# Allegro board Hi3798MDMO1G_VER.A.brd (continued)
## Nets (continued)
$16N1158: J25.11 R79.1
$16N1159: J25.7 J25.8 R270.2
$16N1160: R271.2 T2.15
$16N1161: R269.2 T2.10
$16N1163: J25.6 T2.9
$16N1164: J25.3 T2.11
$16N1165: C23.1 R269.1 R270.1 R271.1 R272.1
$16N1166: J25.1 T2.16
$16N1167: J25.2 T2.14
$16N1168: J25.4 J25.5 R272.2
$16N1169: C153.1 C307.1 T2.2
$16N1187: R61.2 T2.1
$16N1188: R62.2 T2.3
$16N1189: R63.2 T2.6
$16N1190: R64.2 T2.8
$18N880: D19.1 R268.1

Pads without a net: ID1 1; ID2 1; ID3 1; ID4 1; ID5 1; ID6 1; J2 1 6 8 11; J26 14; J34 6; M20 1; M21 1; M22 1; M23 1; T2 4 5 12 13; U1 14 15 56 99 100 101; U2 3; U3 J1 J9 L1 L9; U6 J1 J9 L1 L9; U7 4 9 10; U11 5; U13 5; U19 3 4 5 6 10 11 14 15 20 21 22 26 27 28 33 35 40 45 46 47; U22 1 2 A4 A6 A9 A11 AA1 AA2 AA7 AA8 AA9 AA10 AA11 AA12 AA13 AA14 AE1 AE14 AG2 AG13 AH4 AH6 AH9 AH11 B2 B13 D1 D14 H1 H2 H6 H7 H8 H9 H10 H11 H12 H13 H14 J1 J7 J8 J9 J10 J11 J12 J13 J14 K1 K3 K5 K7 K8 K9 K10 K11 K12 K13 K14 L1 L2 L3 L4 L12 L13 L14 M1 M2 M3 M5 M8 M9 M10 M12 M13 M14 N1 N2 N3 N10 N12 N13 N14 P1 P2 P3 P10 P12 P13 P14 R1 R2 R3 R5 R12 R13 R14 T1 T2 T3 T5 T12 T13 T14 U1 U2 U3 U6 U7 U10 U12 U13 U14 V1 V2 V3 V12 V13 V14 W1 W2 W3 W7 W8 W9 W10 W11 W12 W13 W14 Y1 Y3 Y6 Y7 Y8 Y9 Y10 Y11 Y12 Y13 Y14

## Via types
v1: diameter 0.508, hole 0.254, TOP to BOTTOM, 1049 vias
v2: diameter 0.457, hole 0.203, TOP to BOTTOM, 246 vias

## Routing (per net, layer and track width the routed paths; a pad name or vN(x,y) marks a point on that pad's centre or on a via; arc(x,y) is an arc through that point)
1V1_CORE: length 70.2
  TOP w0.203: U1.168 v1(46.25,43.78) ; U1.30 v1(58.75,23.65) ; v1(48.35,46.74) 48.75,47.13 U1.158 ; v1(48.48,23.65) 48.35,23.52 U1.4 ; U1.134 58.35,47.03 58.64,46.74 v1(59.02,46.74) ; U1.39 v1(62.35,23.65) ; U1.49 66.35,23.24 65.97,23.62 v1(65.37,23.62) ; U1.10 v1(50.75,23.65) ; U1.186 45.99,36.58 v1(46.25,36.83) ; U1.105 v1(69.36,44.58) ; v1(69.31,33.53) 69.56,33.78 U1.78 ; U1.180 v1(46.25,38.98) ; U1.214 v1(46.25,25.38) ; U1.193 v1(46.25,33.78) ; U1.202 v1(46.25,30.18) ; U1.118 64.75,46.93 v1(64.88,46.8) ; U1.86 v1(69.31,36.98)
  TOP w0.381: v1(57.88,9.65) R101.2 C82.2
  BOTTOM w0.381: v1(48.48,42.67) 47.34,43.81 46.21,43.81 ; C1.1 v1(65.37,23.62) ; C62.1 v1(59.02,46.74) 59.04,46.72 LB31.1 ; 46.24,36.83 v1(48.86,36.83) ; 46.24,36.83 v1(46.25,36.83) ; 46.24,36.83 C127.1 ; v1(66.36,31.14) 66.11,30.88 LB21.1 ; v1(69.36,44.58) 69.56,44.58 69.57,44.58 C189.1 ; C128.1 46.13,38.86 v1(46.25,38.98) v1(48.86,38.98) ; C73.1 62.45,23.55 v1(62.35,23.65) ; C107.1 46.24,33.78 v1(46.25,33.78) v1(48.86,33.78) ; v1(48.35,46.74) C130.1 ; C120.1 46.23,25.4 v1(46.25,25.38) v1(48.86,25.38) ; v1(69.31,36.98) 69.33,36.96 C121.1 ; v1(48.48,23.65) 48.35,23.52 C70.1 ; v1(50.75,23.65) 50.77,23.63 C66.1 ; 69.18,19.68 64.8,15.3 59.52,15.3 57.88,13.67 v1(57.88,9.65) ; 46.21,43.81 v1(46.25,43.78) ; 46.21,43.81 C129.1 ; v1(58.75,23.65) 58.77,23.63 C64.1 ; C193.1 46.2,30.23 v1(46.25,30.18) v1(48.86,30.18)
  vias: v1(63.72,45.97) v1(63.72,45.09) v1(68.29,24.89) v1(68.93,24) v1(69.18,23.11) v1(69.31,21.08) v1(70.71,23.62) v1(70.71,21.97)
1V1_CPU: length 13.3
  TOP w0.203: U1.98 71.62,41.78
  TOP w0.254: R53.2 62.48,56.5 62.99,55.99 C76.2 63.4,55.46 63.4,54.32 66.77,50.95 69.72,50.95 70.33,51.56 70.83,51.56
  vias: v1(72.23,41.66) v1(72.23,40.77) v1(72.23,39.88) v1(72.99,50.8) v1(72.99,49.91) v1(73.25,41.66) v1(73.25,40.77) v1(73.25,39.88) v1(73.88,50.8) v1(73.88,49.91) v1(74.64,39.75) v1(74.77,50.8) v1(74.77,49.91)
1V5_DDR3: length 100
  TOP w0.203: U1.35 v1(60.75,23.65) ; v2(35.91,26.04) 35.09,26.86 35.09,27.2 35.44,27.55 35.44,27.62 35.47,27.65 U6.H2 ; U1.165 v1(46.32,44.98) ; U1.190 v1(46.25,34.98) ; U1.25 v1(56.75,23.65) ; U1.44 v1(64.35,23.65) ; U1.183 v1(46.25,37.78) ; v1(66.64,23.62) 67.72,23.62 67.95,23.39 U1.53 ; U1.205 v1(46.25,28.98) ; U1.199 v1(46.25,31.38) ; U1.174 v1(46.25,41.38) ; U1.7 v1(49.55,23.65) ; U1.208 v1(46.25,27.78) ; U1.171 v1(46.25,42.58) ; U1.13 v1(51.95,23.65) ; U1.196 v1(46.25,32.58) ; U1.1 v1(47.1,23.65) ; U1.16 v1(53.15,23.65)
  TOP w0.254: U6.K2 v2(34.27,27.44) ; U3.R1 v2(29.47,44.65) ; U3.N1 v2(31.07,44.65) ; U3.K2 v2(33.47,44.65)
  TOP w0.305: U6.C9 v2(39.47,21.69) ; U6.K8 v2(33.46,22.64) ; U6.N9 v2(31.47,21.69) ; v2(37.07,29.19) 37.07,28.64 U6.F1 ; U6.A1 41.07,28.64 v2(41.07,29.19) ; U3.C1 v2(39.47,45.6) ; U6.H9 35.47,21.73 35.46,21.72 v2(35.42,21.72) ; U3.N9 v2(31.47,38.03) ; U6.R9 v2(29.87,21.69) ; U6.B2 v2(40.66,27.46) ; U3.G7 v2(36.67,40.65) ; U6.N1 v2(31.47,29.19) ; U6.R1 v2(29.87,29.19) ; U6.E9 v2(37.87,21.69) ; v2(38.26,44.65) 38.66,44.25 U3.D2 ; U3.A8 v2(40.67,39.05) ; U3.B2 40.27,44.27 v2(39.88,44.66) ; U3.H9 v2(35.47,38.11) ; U3.D9 v2(39.07,38.25) ; U3.R9 v2(29.87,38.1) ; U6.C1 v2(39.47,29.19) ; U3.E9 v2(38.27,38.25) ; U3.K8 v2(33.47,39.05) ; U3.A1 v2(41.07,45.6) ; U6.D2 v2(39.06,27.46) ; U3.H2 v2(35.06,43.85) ; U6.A8 v2(41.65,23.04) ; U3.F1 v2(37.07,45.63) ; U6.D9 v2(38.67,21.69) ; U6.G7 v2(36.68,24.25) ; U3.C9 v2(39.87,38.25)
  TOP w0.381: 22.07,39.12 22.07,38.1 21.6,37.64 14.16,37.64 C84.2 R10.2 ; R92.1 C103.1 32.12,18.26 v2(31.72,18.67) ; v2(31.88,35.18) 32.16,34.9 C100.1 R60.1
  BOTTOM w0.254: v2(33.46,22.64) 33.7,22.4 C226.1 ; C240.1 37.71,21.85 v2(37.87,21.69) ; C225.1 35.88,22.18 v2(35.42,21.72)
  BOTTOM w0.305: C231.1 39.82,22.04 v2(39.47,21.69) ; v2(41.65,23.04) 41.52,22.92 C238.1 ; C229.1 34.28,27.43 v2(34.27,27.44) ; v2(29.87,38.1) 29.87,37.51 C216.1 ; v2(31.47,38.03) 31.47,37.51 C213.1 ; v2(33.47,39.05) 33.49,39.08 C212.1 ; C239.1 38.9,21.93 v2(38.67,21.69)
  BOTTOM w0.381: v2(40.67,39.05) 40.71,39.01 C218.1 ; C219.1 39.84,38.23 v2(39.87,38.25) ; v2(33.47,44.65) 33.09,44.27 C201.1 ; v2(41.07,29.19) 41.37,28.89 C235.1 ; C202.1 41.52,46.01 41.12,45.6 v2(41.07,45.6) ; C206.1 35.54,38.04 v2(35.47,38.11) ; v2(39.88,44.66) 39.95,44.73 C205.1 ; v2(39.47,45.6) 39.74,45.88 C203.1 ; v2(36.68,24.25) 36.61,24.19 C258.1 ; v2(38.26,44.65) 38.45,44.46 C204.1 ; C211.1 v2(36.67,40.65) ; C215.1 29.53,44.71 v2(29.47,44.65) ; v2(29.87,29.19) 29.87,29.82 C233.1 ; C228.1 29.87,20.92 v2(29.87,21.69) ; v1(53.15,23.65) 53.18,23.62 C97.1 ; R54.1 v2(33.97,47.58) ; C52.1 46.21,42.55 v1(46.25,42.58) ; v2(38.27,38.25) 38.06,38.05 C221.1 ; v2(39.06,27.46) 38.9,27.62 C237.1 ; v1(46.25,34.98) 46.07,34.8 C48.1 ; v1(51.95,23.65) 51.91,23.61 C109.1 ; v1(46.25,27.78) 46.21,27.81 C125.1 ; C20.1 66.82,23.44 v1(66.64,23.62) ; C101.1 46.24,31.37 v1(46.25,31.38) ; v2(37.07,29.19) 36.71,28.83 C232.1 ; C236.1 40.52,27.59 v2(40.66,27.46) ; v1(46.25,28.98) 46.22,28.96 C94.1 ; v1(46.25,37.78) 46.18,37.85 C49.1 ; v2(37.07,45.63) 37.07,45.39 C209.1 ; v1(47.1,23.65) 47.08,23.63 C96.1 ; v1(56.75,23.65) 56.74,23.63 C137.1 ; C98.1 46.18,32.51 v1(46.25,32.58) ; C234.1 39.66,29 v2(39.47,29.19) ; C102.1 60.8,23.6 v1(60.75,23.65) ; R78.1 v2(37.13,33.05) ; v2(31.47,29.19) 31.47,29.78 C230.1 ; v1(64.35,23.65) 64.35,23.64 64.1,23.64 63.85,23.39 C104.1 ; v1(46.25,41.38) 46.22,41.4 C99.1 ; C210.1 35.57,43.34 v2(35.06,43.85) ; v2(31.47,21.69) 31.47,21.11 C227.1 ; C223.1 v2(37.13,32.16) ; v2(39.07,38.25) 38.95,38.14 C220.1 ; v2(31.07,44.65) 31.23,44.81 C214.1 ; C117.1 49.62,23.58 v1(49.55,23.65) ; C208.1 v2(34.86,47.58) ; v1(46.32,44.98) 46.3,44.96 C92.1
  vias: v1(23.41,41.25) v1(23.41,39.88) v1(24.02,39.24) v1(24.05,42.95) v1(24.05,41.96) v1(24.07,40.51) v2(35.91,25.32) v2(36.54,41.59) v2(37.43,41.59) v2(44.67,22.99) v2(44.67,22.1) v2(45.56,22.99) v2(45.56,22.1) v2(46.45,22.99) v2(46.45,22.1)
3V3: length 23.3
  TOP w0.203: v1(71.85,28.7) 71.73,28.58 U1.65
  TOP w0.381: v1(64.76,10.54) 64.79,10.52 64.79,10.49 64.97,10.31 R31.1 ; R136.1 v1(78.68,4.65) ; R6.1 v1(14.39,39.29) ; R140.2 v1(67.79,7.24) ; R2.1 v1(57.88,7.11) ; J18.4 76.88,4.02 R135.1 v1(76.04,5.33) ; R178.2 v1(69.06,7.11) ; R34.1 v1(66.8,5.97)
  BOTTOM w0.381: v1(65.98,68.86) 65.3,68.86 R105.2 ; R88.2 73.27,26.26 72.99,26.54 v1(72.87,26.54) ; Q13.2 67.4,9.78 v1(66.9,9.27) ; v1(14.39,39.29) 14.13,39.54 14.13,44.88 C114.1
  vias: v1(12.12,46.38) v1(12.12,45.61) v1(12.12,44.85) v1(12.89,46.38) v1(12.89,45.61) v1(12.89,44.85) v1(59.96,14.35) v1(60.6,12.7) v1(60.67,13.79) v1(61.36,13.13) v1(61.69,13.98) v1(62.83,14.1) v1(66.64,69.93) v1(67.02,59.19) v1(67.15,69.16) v1(67.66,69.93) v1(67.91,59.19) v1(68.17,69.16) v1(68.67,69.93) v1(68.8,59.19) v1(69.18,69.16) v1(69.69,69.93) v1(69.69,59.19) v1(70.58,59.19)
3V3_MOS: length 54.3
  TOP w0.203: v1(69.31,31.93) 69.56,32.18 U1.74 ; U1.120 63.95,47.01 64,46.96 v1(64,46.77) ; v1(69.37,43.69) 69.37,43.81 69.73,44.18 U1.104 ; U1.83 v1(69.31,35.78)
  TOP w0.381: v1(62.96,72.77) 62.96,72.58 62.77,72.39 D9.2 61.51,72.08 v1(61.51,70.1) ; v1(47.68,66.04) D19.2 ; v1(17.81,63.93) R26.1 18.2,64.7 18.58,65.09 18.58,67.99 17.94,68.63 17.94,75.25 19.5,76.8 J25.10 ; v1(65.88,75.82) R25.1 ; J25.12 32.61,76.8 33.33,76.08 33.33,64.53 33.59,64.27 R30.1 34.04,63.79 31.74,61.49 v1(31.69,61.49)
  BOTTOM w0.381: v1(18.25,60.37) 18.25,63.49 v1(17.81,63.93) ; v1(64,46.77) C197.1 63.98,47.52 R39.2 ; C199.1 69.36,31.88 v1(69.31,31.93) ; v1(65.88,75.82) 65.88,75.69 v1(62.96,72.77)
  vias: v1(14.06,53.77) v1(14.06,53.01) v1(18.25,59.23) v1(20.23,26.72) v1(52.29,43.31) v1(52.29,42.42) v1(55.29,43.1) v1(55.29,42.21) v1(58.26,28.19) v1(58.26,27.3) v1(60.04,58.27) v1(60.04,57.38) v1(60.42,43.43) v1(60.42,42.55) v1(65.37,28.19) v1(65.37,27.3) v1(65.75,36.45) v1(65.75,35.56) v1(66.01,12.57) v1(66.9,12.57) v2(20.23,25.7) v2(21.12,26.72) v2(21.12,25.7)
3V3_MOS_FLASH: length 42.1
  TOP w0.203: U22.Y4 U22.AA3
  TOP w0.254: U19.1 90.11,44.68 89.76,44.32 v1(87.72,44.32) ; v1(80.49,45.09) 79.09,45.09 78.61,45.56 U19.24 ; U19.37 84.61,28.01 v1(84.61,28.01) ; 85.11,35.9 v2(85.07,35.94) ; 85.11,35.9 85.13,35.87 U22.N5 ; 85.11,35.9 U22.M6 ; U22.K6 85.11,34.5 v2(84.75,34.86) 82.94,34.86 82.58,35.22 82.58,37 82.95,37.37 U22.T10 83.62,37.37 v2(83.64,37.36) 83.64,37.84 U22.U9 83.61,38.02 v2(83.28,38.35) ; v1(83.11,25.36) U19.34 ; 84.61,45.33 U19.12 ; v2(85.74,40.43) 85.61,40.3 U22.AA5 ; U22.AA3 86.61,39.89 v2(87.15,40.43) ; R68.2 84.96,24.18 83.97,24.18 83.64,24.51 R80.1 ; U22.Y4 U22.W4 v2(86.11,38.34)
  TOP w0.381: v2(87.15,40.43) 87.15,41.22 86.75,41.63 86.04,41.63 85.74,41.32 v2(85.74,40.43) ; v1(83.03,24.38) 83.41,24.77 R80.1 ; v2(84.48,43.4) 84.61,43.53 84.61,45.33
  BOTTOM w0.381: C275.1 84.68,34.8 v2(84.75,34.86) ; v2(83.64,37.36) 83.63,37.36 C105.1 ; C93.1 85.31,36.19 v2(85.07,35.94) ; v2(84.48,43.4) 84.07,43.81 82.39,43.81 81.76,44.45 81.76,44.7 81.37,45.09 v1(80.49,45.09) ; R212.1 83.32,38.39 v2(83.28,38.35) ; v2(85.74,40.43) 85.68,40.37 C323.1 86.11,39.29 v2(86.11,38.34)
  vias: v1(75.15,58.93) v1(75.15,58.04) v1(76.04,58.93) v1(76.04,58.04)
3V3_SD:
  vias: v1(10.27,56.08) v1(10.27,55.29)
3V3_WIFI:
  vias: v1(14.26,27.48) v1(15.15,27.48)
5V0: length 11.8
  TOP w0.254: v1(74.01,13.34) 73.88,13.21 R144.1
  BOTTOM w0.381: v1(72.48,62.99) 71.01,62.99 70.2,62.18 D4.2 69.88,61.43 63.79,61.43 R4.1
  vias: v1(73.25,13.84) v1(73.25,12.83) v1(74.71,72.06) v1(74.71,71.17) v1(74.71,70.28) v1(75.6,72.06) v1(75.6,71.17) v1(75.6,70.28) v1(76.49,72.06) v1(76.49,71.17) v1(76.49,70.28)
5V0_MOS: length 21.6
  TOP w0.381: D20.2 v1(52.87,77.1) ; R11.2 v1(75.36,14.73) ; R15.2 v1(80.49,69.09)
  BOTTOM w0.381: v1(80.49,69.09) 80.1,68.71 73.88,68.71 72.05,70.54 64.79,70.54 63.47,69.22 R179.1
  vias: v1(78.45,74.8) v1(79.34,74.8) v1(80.23,74.8) v1(80.36,13.21) v1(80.36,12.32) v1(80.36,11.43)
5V0_MOS_HDMI: length 14
  TOP w0.254: 49.41,78.17 49.17,78.41 J26.18
  TOP w0.381: U4.5 v1(50.96,73.42) 51.68,73.42 52.1,73.84 D20.1 52.1,75.1 51.48,75.73 R187.2 v1(50.73,76.49) 49.41,77.81 49.41,78.17 ; R186.2 v1(48.95,76.49)
  BOTTOM w0.381: v1(50.96,73.42) 50.88,73.34 C150.1 ; v1(48.95,76.49) v1(50.73,76.49)
AVDD11_PLL012: length 1.5
  TOP w0.203: v1(69.39,30.35) 69.39,30.07 69.68,29.78 U1.68
AVDD33_PLL01: length 1.3
  TOP w0.203: U1.66 69.69,28.98 69.39,28.68 v1(69.39,28.57)
AVDD33_USB2: length 1.4
  TOP w0.203: v1(69.31,38.16) 69.31,38.03 69.56,37.78 U1.88
GND: length 633.7
  TOP w0.089: 88.12,39.62 87.36,39.62 U22.Y2
  TOP w0.203: U1.62 72.03,27.38 v1(72.23,27.18) ; v1(54.2,21.34) 54.35,21.49 U1.19 ; U1.94 v1(69.31,40.18) ; U1.97 v1(69.31,41.38) ; U1.177 v1(43.91,40.18) ; 35.06,40.55 35.06,39.85 U3.J8 ; U22.AA6 U22.Y5 U22.AA4 ; v1(69.39,29.38) U1.67 71.51,29.38 v1(71.72,29.59) ; v2(34.38,24.29) 34.28,24.18 34.28,23.63 34.67,23.24 U6.J8 ; U1.115 v1(65.95,48.99) ; U1.110 67.95,48.73 67.72,48.96 v1(67.53,48.96) ; U1.211 v2(43.82,26.58)
  TOP w0.229: U22.K4 85.62,34.86 v2(85.57,34.86)
  TOP w0.254: v1(69.06,51.44) 67.15,51.44 v1(65.25,53.34) ; v2(84.84,40.46) 85.11,40.19 U22.AA6 ; v1(83.65,28.01) 83.9,28.01 84.11,27.8 U19.36 ; J26.11 v1(45.67,78.31) ; v1(71.34,50.93) 71.85,50.42 C72.2 ; U3.E2 37.79,44.33 37.79,44.97 U3.E1 ; R149.2 v1(27.8,50.56) ; v2(86.45,41.04) 86.44,41.04 86.44,40.48 86.11,40.15 U22.AA4 ; J26.2 v1(41.17,78.31) ; J26.8 v1(44.17,78.31) ; v1(79.11,47.53) U19.23 ; U3.M1 v2(32.67,44.65) ; U19.48 v1(90.11,28.07) ; v1(78.61,28.19) U19.25 ; J26.17 v1(48.67,78.31) ; v1(89.48,45.09) 89.61,45.21 U19.2 ; J26.5 v1(42.67,78.31) ; 83.96,45.13 84.11,45.28 U19.13 ; U3.P1 v2(30.27,44.65) ; U6.J2 v2(34.27,28.24) ; U3.J2 v2(35.07,44.65) ; U3.T1 v2(28.67,44.65)
  TOP w0.305: U3.P9 v2(30.27,39.05) ; U3.F9 v2(37.07,38.11) ; v2(40.73,26.5) 40.27,26.97 U6.B3 ; U3.B9 v2(39.87,39.05) ; U3.M9 v2(32.27,38.1) ; v2(40.36,21.72) 40.27,21.81 U6.B9 ; U3.G1 v2(36.27,45.63) ; v2(36.24,21.69) 36.29,21.69 36.27,21.72 U6.G9 ; U3.A9 v2(40.67,38.25) ; U3.D1 v2(38.26,45.46) 37.87,45.07 U3.E1 ; U6.B1 v2(40.27,29.19) ; U6.A9 41.07,22.14 v2(41.5,21.72) ; U3.D8 v2(39.07,39.05) ; v1(42.53,76.08) v1(42.53,74.62) v1(42.53,73.01) ; U6.G1 v2(36.27,29.61) ; U3.G9 v2(36.27,38.11) ; v1(40.93,73.06) U23.3 U23.8 v1(40.93,76.09) ; U6.E8 v2(38.27,23.44) U6.D8 ; U6.P9 v2(30.67,21.69) ; v2(37.07,21.69) 37.09,21.69 37.07,21.72 U6.F9 ; v1(44.11,76.04) U24.8 U24.3 v1(44.11,73.06) ; U6.T1 v2(28.68,29.03) ; v2(35.47,41.01) 35.06,40.61 35.06,40.55 ; U6.D1 v2(38.67,29.19) ; U6.E1 37.87,28.62 v2(38.26,28.23) U6.E2 ; v2(25.62,26.16) 26.05,26.59 C314.2 ; U3.E8 v2(38.27,39.05) ; U6.M1 v2(32.27,29.19) ; U6.P1 v2(30.67,29.19) ; U3.B3 40.27,43.47 v2(39.88,43.86) ; U6.T9 v2(29.07,21.69) ; U3.G8 v2(36.67,39.85) ; U3.B1 v2(40.27,45.6) ; U6.M9 v2(32.27,21.69) ; U6.G8 v2(36.68,23.45) ; U3.T9 v2(29.07,38.1)
  TOP w0.356: U5.10 v1(58.71,68.89) ; 56.45,72.1 v1(56.45,72.06) ; 56.45,72.1 R146.2 ; 56.45,72.1 55.83,71.49 v1(55.15,71.49) U5.1 ; R145.2 v1(57.54,72.06) 58.11,71.49 v1(58.58,71.49) U5.14 ; v1(55.21,68.96) 55.21,69.28 54.96,69.54 U5.4
  TOP w0.381: C5.2 v1(65.78,10.64) ; R24.1 v1(74.64,36.58) R87.1 ; v1(57.88,58.42) 57.59,58.71 R50.2 ; v1(61.72,10.64) 61.05,10.64 R13.1 ; R9.2 C79.2 v1(64.08,71.75) ; C158.2 63.21,67.44 63.85,68.07 v1(63.85,68.33) ; 83.96,45.13 83.11,44.28 83.11,42.87 v2(83.02,42.77) ; v2(36.77,34.9) R55.2 C86.2 ; C118.2 v1(80.49,5.71) ; R51.2 64,10.64 v1(63.72,10.92) ; v2(36.04,18.26) R93.2 C87.2 ; C22.2 v1(47.47,51.94) ; U4.2 v1(46.23,73.42) ; C141.2 v1(78.83,60.5) ; Q4.2 v1(68.93,9.02) ; C33.1 v1(51.32,66.93) ; R52.2 v1(10.45,38.37) ; C71.2 v1(67.91,50.42) ; C365.2 v1(77.06,22.12) ; v1(59.28,6.73) 59.27,6.74 Q1.2 ; J21.14 v1(11.34,48.07) ; C364.2 73.5,21.34 v1(73.25,21.59) ; v1(58.39,62.6) C316.2 ; D1.2 v1(80.61,64.01) ; C139.2 v1(78.71,63.22) ; X2.2 v1(78.71,18.07) ; R48.1 v1(82.52,69.95) ; R99.1 63.21,58.04 ; v1(64.23,7.62) 63.8,8.05 Q2.2 ; v1(66.77,18.8) 66.9,18.92 C37.2 67.85,19.37 67.63,19.58 R45.2 67.63,20.55 68.04,20.95 v1(68.04,21.21) ; R57.2 v1(62.3,71.25) ; C177.2 v1(72.99,6.38) ; C363.2 v1(50.64,68.07) ; v1(55.26,58.37) 54.93,58.7 R183.2 ; C317.2 v1(53.76,62.6) ; U11.2 v1(65.12,56.64) ; D6.2 v1(81.37,60.5)
  TOP w0.508: v1(10.12,57.32) 9.8,57.64 J21.6 7.87,57.64 ; J12.5 85.79,57.24 ; J12.5 87.75,55.28 ; J12.5 85.79,53.33 ; J12.5 83.83,55.28 ; J12.6 87.75,68.42 ; J12.6 83.83,68.42 ; J12.6 85.79,66.47 ; J12.6 85.79,70.38 ; J12.4 83.08,66.42 ; J12.4 81.7,65.35 ; J12.4 84.46,65.35 ; J12.4 83.08,64.29 ; LED1.2 v1(62.09,5.21)
  TOP w0.635: J34.5 63.36,77.65 ; J34.5 62.11,79.25 ; J34.5 62.11,76.05 ; S1.4 65.75,83.35 ; S1.4 64.3,81.9 ; S1.4 65.75,80.46 ; S1.1 71.5,85.6 ; S1.1 72.69,84.4 ; S1.1 71.5,83.21 ; S1.1 70.31,84.4 ; J1.2 75.57,82.31 ; J1.2 76.84,80.2 ; J1.2 75.57,78.09 ; J1.2 74.3,80.2 ; 78.49,85.38 J10.2 ; J10.2 80.37,86.66 ; J10.2 82.25,85.38 ; J26.21 39.12,80.8 ; J26.21 37.92,78.72 ; J26.21 36.73,80.8 ; J26.21 37.92,82.88 ; S1.3 74.2,81.9 ; S1.3 71.3,81.9 ; S1.3 72.75,83.35 ; S1.3 72.75,80.46 ; J26.20 52.42,82.88 ; J26.20 53.62,80.8 ; J26.20 52.42,78.72 ; J26.20 51.23,80.8 ; J13.4 82.3,18.79 ; J13.4 82.3,16.75 ; J13.4 83.63,17.77 ; J13.4 80.97,17.77 ; 80.63,1.24 J18.1 ; J18.1 81.44,2.24 ; J18.1 80.63,3.25 ; 85.01,18.94 J13.6 ; J13.6 86.91,20.84 ; J13.6 83.1,20.84 ; 51.23,86.76 J26.22 ; J26.22 53.62,86.76 ; J26.22 52.42,84.93 ; 37.92,84.93 J26.23 ; J26.23 36.73,86.76 ; J26.23 39.12,86.76 ; 82.48,83.7 J1.3 80.37,82.48 ; 85.01,5.74 J13.5 ; J13.5 86.97,7.7 ; J13.5 85.01,9.66 ; J13.5 83.05,7.7 ; 77.67,81.3 J10.3 ; J10.3 77.67,85.06 ; J10.3 76.39,83.18
  GND02 w0.635: J18.1 80.63,3.17 ; J18.1 80.63,1.32 ; J18.1 81.37,2.24 ; J12.4 84.39,65.35 ; J12.4 81.77,65.35 ; J12.4 83.08,64.36 ; J12.4 83.08,66.34 ; 69.58,1.13 D3.2 ; D3.2 70.57,2.12 ; D3.2 69.58,3.11 ; D3.2 68.59,2.12 ; 20.03,34.4 J2.2 20.03,36.64 ; J12.6 85.79,70.3 ; J12.6 85.79,66.54 ; J12.6 87.67,68.42 ; J12.6 83.91,68.42 ; 10.43,8.52 J2.7 ; J2.7 11.42,7.53 ; J2.7 11.42,9.51 ; 85.01,5.82 J13.5 ; J13.5 86.89,7.7 ; J13.5 85.01,9.58 ; J13.5 83.13,7.7 ; J2.10 19.7,9.51 ; J2.10 18.71,8.52 ; J2.10 19.7,7.53 ; 72.75,80.53 S1.3 ; S1.3 71.38,81.9 ; S1.3 72.75,83.28 ; S1.3 74.12,81.9 ; 85.01,18.96 J13.6 ; J13.6 85.01,22.72 ; J13.6 86.89,20.84 ; J13.6 83.13,20.84 ; 62.11,76.13 J34.5 ; J34.5 63.28,77.65 ; J34.5 62.11,79.18 ; J2.12 22.7,9.51 ; J2.12 22.7,7.53 ; J2.12 23.69,8.52 ; 87.94,51.18 J3.1 ; J3.1 90.3,51.18 ; J3.1 89.12,52.36 ; J3.1 89.12,50 ; 62.09,1 LED1.2 ; LED1.2 60.97,2.12 ; LED1.2 62.09,3.24 ; LED1.2 63.2,2.12 ; J26.20 52.42,82.81 ; J26.20 52.42,78.79 ; J26.20 51.3,80.8 ; J26.20 53.54,80.8 ; S1.4 67.12,81.9 ; S1.4 65.75,80.53 ; S1.4 65.75,83.28 ; S1.4 64.38,81.9 ; J10.2 80.37,86.63 ; J10.2 78.52,85.38 ; J10.2 82.23,85.38 ; 75.57,78.12 J1.2 ; J1.2 75.57,82.28 ; J1.2 76.82,80.2 ; J1.2 74.33,80.2 ; S1.1 71.5,85.52 ; S1.1 70.38,84.4 ; S1.1 71.5,83.29 ; S1.1 72.62,84.4 ; J12.5 85.79,57.16 ; J12.5 83.91,55.28 ; J12.5 87.67,55.28 ; J12.5 85.79,53.4 ; 52.42,85.01 J26.22 ; J26.22 51.3,86.76 ; J26.22 53.54,86.76 ; 36.8,80.8 J26.21 ; J26.21 39.04,80.8 ; J26.21 37.92,82.81 ; J26.21 37.92,78.79 ; 80.37,82.5 J1.3 82.46,83.7 ; 36.8,86.76 J26.23 ; J26.23 39.04,86.76 ; J26.23 37.92,85.01 ; 77.67,81.32 J10.3 ; J10.3 76.42,83.18 ; J10.3 77.67,85.03 ; J2.9 15.41,8.52 ; J2.9 14.42,7.53 ; J2.9 14.42,9.51 ; 80.99,17.77 J13.4 ; J13.4 82.3,18.76 ; J13.4 82.3,16.78 ; J13.4 83.61,17.77
  POWER03 w0.635: 37.92,85.01 J26.23 ; J26.23 39.04,86.76 ; J26.23 36.8,86.76 ; J18.1 80.63,3.17 ; J18.1 81.37,2.24 ; J18.1 80.63,1.32 ; J13.5 85.01,9.58 ; J13.5 86.89,7.7 ; J13.5 83.13,7.7 ; J13.5 85.01,5.82 ; 51.3,86.76 J26.22 ; J26.22 53.54,86.76 ; J26.22 52.42,85.01 ; S1.1 72.62,84.4 ; S1.1 70.38,84.4 ; S1.1 71.5,83.29 ; S1.1 71.5,85.52 ; S1.4 67.12,81.9 ; S1.4 65.75,83.28 ; S1.4 65.75,80.53 ; S1.4 64.38,81.9 ; S1.3 74.12,81.9 ; S1.3 72.75,83.28 ; S1.3 71.38,81.9 ; S1.3 72.75,80.53 ; J10.3 77.67,85.03 ; J10.3 77.67,81.32 ; J10.3 76.42,83.18 ; D3.2 69.58,3.11 ; D3.2 70.57,2.12 ; D3.2 68.59,2.12 ; D3.2 69.58,1.13 ; J3.1 90.3,51.18 ; J3.1 89.12,52.36 ; J3.1 89.12,50 ; J34.5 63.28,77.65 ; J34.5 62.11,79.18 ; J34.5 62.11,76.13 ; J26.20 53.54,80.8 ; J26.20 52.42,82.81 ; J26.20 51.3,80.8 ; J26.20 52.42,78.79 ; 83.91,68.42 J12.6 ; J12.6 87.67,68.42 ; J12.6 85.79,66.54 ; J12.6 85.79,70.3 ; J2.7 11.42,9.51 ; J2.7 11.42,7.53 ; J2.7 10.43,8.52 ; J10.2 82.23,85.38 ; J10.2 80.37,86.63 ; J10.2 78.52,85.38 ; 75.57,78.12 J1.2 ; J1.2 76.82,80.2 ; J1.2 74.33,80.2 ; J1.2 75.57,82.28 ; J2.9 15.41,8.52 ; J2.9 14.42,9.51 ; J2.9 14.42,7.53 ; 82.46,83.7 J1.3 80.37,82.5 ; 36.8,80.8 J26.21 ; J26.21 37.92,78.79 ; J26.21 37.92,82.81 ; J26.21 39.04,80.8 ; LED1.2 63.2,2.12 ; LED1.2 62.09,1 ; LED1.2 62.09,3.24 ; LED1.2 60.97,2.12
  BOTTOM w0.254: v2(37.07,21.69) 36.75,22.02 C225.2 ; C240.2 37.97,23.15 v2(38.27,23.44) ; 55.29,48.45 55.28,48.45
  BOTTOM w0.305: v2(40.36,21.72) 40.36,21.99 C238.2 ; C313.2 27.98,44.41 28.2,44.64 28.66,44.64 v2(28.67,44.65) ; v2(33.12,41.2) 33.12,41.01 33.49,40.64 C212.2 ; v2(30.29,31.22) 29.83,30.77 C233.2 ; v2(34.38,25.47) 34.38,25.94 C229.2 ; v2(38.27,23.44) 38.57,23.15 C239.2 C231.2 ; v2(33.12,41.91) 32.98,42.04 R46.1 ; R71.1 v2(33.54,25.44) ; C258.2 36.6,23.37 v2(36.68,23.45)
  BOTTOM w0.381: v2(40.27,45.6) 40.35,45.69 40.35,45.87 C202.2 ; C391.2 10.13,57.34 v1(10.12,57.32) ; v2(34.02,20.51) 33.7,20.84 C226.2 ; C210.2 35.57,44.15 v2(35.07,44.65) ; v2(31.86,36) 31.86,36.31 C213.2 ; C7.2 53.69,43.28 v1(53.66,43.26) ; C230.2 v2(31.51,31.22) ; v2(38.67,29.19) 38.85,29.01 C234.2 38.58,28.56 v2(38.26,28.23) ; C235.2 40.55,28.91 v2(40.27,29.19) ; C334.2 v1(59.05,43.31) ; v2(28.67,44.65) 28.72,44.7 C215.2 ; C201.2 32.27,44.26 v2(32.67,44.65) ; C227.2 31.49,19.82 v2(31.63,19.67) ; v2(37.13,31.27) R84.2 ; v2(36.27,45.63) 35.9,45.26 C209.2 ; R33.2 v1(89.02,28.04) ; C237.2 37.63,26.8 v2(37.48,26.66) 37.36,26.78 C224.2 ; C205.2 39.93,43.92 v2(39.88,43.86) ; C214.2 30.42,44.8 v2(30.27,44.65) ; C271.2 R75.2 v2(31.46,46.87) ; C307.2 v1(23.43,66.15) ; v2(36.27,38.11) 36.35,38.03 C206.2 36.35,36.6 ; C275.2 v2(80.61,34.8) ; S2.4 v1(83.33,47.62) ; v2(37.07,38.11) 37.25,37.93 C221.2 37.25,36.62 ; v1(79.98,43.31) 79.98,44.11 S2.5 ; C236.2 40.46,26.78 v2(40.73,26.5) ; v2(40.67,38.25) 40.72,38.2 C218.2 ; C232.2 35.63,28.97 v2(36.27,29.61) ; v2(84.42,37.34) 84.58,37.49 C93.2 ; C228.2 v2(29.94,19.3) ; C189.2 v1(71.6,44.58) ; C263.2 v1(12.46,58.11) ; v2(84.84,40.46) 84.87,40.44 C323.2 ; C216.2 v2(29.89,36.1) ; C297.2 v1(27.06,66.15) ; C105.2 83.64,36.55 v2(83.66,36.58) ; v2(36.67,39.85) 37.39,39.85 C211.2 ; C154.2 v1(29.78,66.15) ; C153.2 v1(20.84,66.15) ; R210.2 v1(13.78,58.11)
  BOTTOM w0.635: S1.4 65.75,83.35 ; S1.4 64.3,81.9 ; S1.4 65.75,80.46 ; S1.4 67.2,81.9 ; 74.25,80.2 J1.2 ; J1.2 76.89,80.2 ; J1.2 75.57,78.04 ; J1.2 75.57,82.36 ; J12.4 83.08,66.42 ; J12.4 84.46,65.35 ; J12.4 83.08,64.29 ; J12.4 81.7,65.35 ; 51.23,80.8 J26.20 ; J26.20 53.62,80.8 ; J26.20 52.42,82.88 ; J26.20 52.42,78.72 ; 62.09,0.92 LED1.2 ; LED1.2 62.09,3.31 ; LED1.2 63.28,2.12 ; LED1.2 60.89,2.12 ; 36.73,80.8 J26.21 ; J26.21 37.92,78.72 ; J26.21 37.92,82.88 ; J26.21 39.12,80.8 ; J13.5 85.01,9.58 ; J13.5 83.13,7.7 ; J13.5 86.89,7.7 ; J13.5 85.01,5.82 ; J12.5 85.79,57.24 ; J12.5 83.83,55.28 ; J12.5 87.75,55.28 ; J12.5 85.79,53.33 ; 72.75,80.46 S1.3 ; S1.3 74.2,81.9 ; S1.3 72.75,83.35 ; S1.3 71.3,81.9 ; 80.63,1.24 J18.1 ; J18.1 81.44,2.24 ; J18.1 80.63,3.25 ; 18.64,8.52 J2.10 ; J2.10 19.7,7.07 ; J2.10 19.7,9.96 ; 83.83,68.42 J12.6 ; J12.6 85.79,70.38 ; J12.6 85.79,66.47 ; J12.6 87.75,68.42 ; J2.9 14.42,9.96 ; J2.9 14.42,7.07 ; J2.9 15.49,8.52 ; 70.31,84.4 S1.1 ; S1.1 71.5,85.6 ; S1.1 71.5,83.21 ; S1.1 72.69,84.4 ; 51.23,86.76 J26.22 ; J26.22 53.62,86.76 ; J26.22 52.42,84.93 ; J13.4 82.3,18.76 ; J13.4 82.3,16.78 ; J13.4 80.99,17.77 ; J13.4 83.61,17.77 ; J2.12 22.7,9.96 ; J2.12 23.77,8.52 ; J2.12 22.7,7.07 ; J34.5 63.36,77.65 ; J34.5 62.11,79.25 ; J34.5 62.11,76.05 ; D3.2 69.58,3.18 ; D3.2 69.58,1.05 ; D3.2 70.65,2.12 ; D3.2 68.51,2.12 ; 36.73,86.76 J26.23 ; J26.23 39.12,86.76 ; J26.23 37.92,84.93 ; 89.12,49.92 J3.1 ; J3.1 89.12,52.44 ; J3.1 90.38,51.18 ; J3.1 87.86,51.18 ; J13.6 86.97,20.84 ; J13.6 85.01,18.88 ; J13.6 83.05,20.84 ; J13.6 85.01,22.8 ; 10.35,8.52 J2.7 ; J2.7 11.42,7.07 ; J2.7 11.42,9.96
  vias: v1(7.91,80.69) v1(7.91,78.66) v1(7.91,68.5) v1(7.91,65.96) v1(7.91,63.42) v1(7.91,60.88) v1(7.91,35.99) v1(7.91,33.45) v1(7.91,30.91) v1(7.91,28.37) v1(7.91,8.17) v1(7.91,5.89) v1(8.04,13.25) v1(8.76,30.91) v1(9.05,13.25) v1(9.18,81.96) v1(9.18,79.93) v1(9.18,77.39) v1(9.18,74.85) v1(9.18,72.31) v1(9.18,64.69) v1(9.18,44.88) v1(9.18,42.34) v1(9.18,39.8) v1(9.18,32.18) v1(9.18,29.64) v1(9.18,27.1) v1(9.18,24.56) v1(9.18,22.02) v1(9.18,19.48) v1(9.18,18.08) v1(9.18,8.17) v1(9.18,4.62) v1(10.32,14.52) v1(10.32,13.25) v1(10.32,11.98) v1(10.32,9.7) v1(10.45,46.15) v1(10.45,43.61) v1(10.45,41.07) v1(10.45,23.29) v1(10.45,20.75) v1(10.45,19.48) v1(10.45,18.08) v1(10.45,16.81) v1(10.45,6.78) v1(10.96,83.74) v1(11.34,49.96) v1(11.52,74.8) v1(11.46,16.43) v1(11.52,10.29) v1(11.72,32.18) v1(11.72,30.91) v1(11.72,29.64) v1(11.72,28.37) v1(11.72,27.1) v1(11.72,25.83) v1(11.72,22.02) v1(11.72,19.48) v1(11.78,72.77) v1(11.83,20.75) v1(12.1,13.76) v1(12.1,12.75) v1(12.23,15.54) v1(12.29,10.92) v1(12.86,0.81) v1(13.24,13.76) v1(13.24,12.75) v1(13.24,10.84) v1(13.45,41.47) v1(13.56,74.3) v1(13.56,65.79) v1(13.62,49.96) v1(13.62,48.05) v1(13.63,85.37) v1(13.75,15.54) v1(13.94,71.88) v1(14,61.51) v1(14,19.48) v1(14.13,24.18) v1(14.51,10.84) v1(14.7,86.49) v1(14.7,70.23) v1(14.72,42.95) v1(14.72,41.47) v1(14.72,40.28) v1(14.77,0.81) v1(14.89,14.27) v1(14.89,13.25) v1(14.95,67.31) v1(15.21,5.84) v1(15.27,24.18) v1(15.27,19.48) v1(15.35,46.38) v1(15.53,65.96) v1(15.46,3.43) v1(15.71,52.12) v1(15.66,49.96) v1(15.66,48.05) v1(15.66,11.48) v1(15.78,15.54) v1(16.04,14.4) v1(16.04,9.7) v1(16.04,7.16) v1(16.04,2.08) v1(16.29,46.38) v1(16.29,45.61) v1(16.29,44.85) v1(16.54,24.18) v1(16.54,18.21) v1(16.54,16.94) v1(16.54,12.37) v1(16.8,61.51) v1(16.8,22.02) v1(16.93,15.54) v1(17.31,10.84) v1(17.31,8.43) v1(17.31,0.81) v1(17.43,13.25) v1(17.62,24.13) v1(17.81,19.48) v1(17.94,54.4) v1(17.94,53.13) v1(17.94,51.99) v1(17.94,49.96) v1(17.94,48.05) v1(17.94,41.58) v1(17.94,40.43) v1(18.32,14.27) v1(18.76,22.86) v1(18.96,41.58) v1(18.96,40.43) v1(18.96,39.29) v1(19.21,61.51) v1(19.59,10.84) v1(19.91,22.86) v1(19.91,20.7) v1(19.91,19.43) v1(19.91,14.86) v1(19.97,51.99) v1(19.97,49.96) v1(19.96,33.22) v1(19.96,31.95) v1(20.23,60.5) v1(20.23,59.48) v1(20.48,54.4) v1(21.3,22.86) v1(21.3,20.7) v1(21.3,12.83) v1(22.01,61.39) v1(22.13,10.84) v1(22.32,32.11) v1(22.39,0.81) v1(23.15,51.99) v1(23.15,50.97) v1(23.34,22.86) v1(23.34,20.7) v1(23.44,32.69) v1(23.66,17.32) v1(23.66,14.78) v1(23.66,9.7) v1(23.66,7.16) v1(23.66,4.62) v1(23.66,2.08) v1(23.97,30.48) v1(23.97,29.72) v1(23.97,28.96) v1(24.1,49.53) v1(24.35,38.1) v1(24.93,0.81) v1(25.24,48.01) v1(25.24,46.61) v1(26.2,14.78) v1(26.2,12.24) v1(26.2,7.16) v1(26.2,4.62) v1(26.2,2.08) v1(26.64,49.53) v1(27.47,0.81) v1(28.74,12.24) v1(28.74,9.7) v1(28.74,4.62) v1(28.74,2.08) v1(29.18,52.07) v1(29.18,49.53) v1(30.01,0.81) v1(30.68,8.18) v1(30.78,11.28) v1(31.08,64.44) v1(31.28,9.7) v1(31.28,4.62) v1(31.28,2.08) v1(31.72,52.07) v1(31.72,49.53) v1(32.55,7.67) v1(32.55,0.81) v1(33.82,9.19) v1(33.82,4.62) v1(33.82,2.08) v1(34.28,62.87) v1(34.26,52.07) v1(34.26,49.53) v1(35.09,7.67) v1(35.09,0.81) v1(36.36,87.55) v1(36.36,85.01) v1(36.36,82.47) v1(36.36,78.28) v1(36.36,75.74) v1(36.36,73.2) v1(36.36,70.66) v1(36.36,68.12) v1(36.36,65.58) v1(36.36,63.04) v1(36.36,9.19) v1(36.36,4.62) v1(36.36,2.08) v1(36.8,52.07) v1(36.8,49.53) v1(37.63,7.67) v1(37.63,0.81) v1(38.9,75.74) v1(38.9,73.2) v1(38.9,70.66) v1(38.9,68.12) v1(38.9,65.58) v1(38.9,63.04) v1(38.9,9.19) v1(38.9,4.62) v1(38.9,2.08) v1(39.25,79.03) v1(39.34,49.53) v1(40.04,86.28) v1(40.04,83.74) v1(40.17,7.67) v1(40.17,0.81) v1(41.31,87.55) v1(41.31,85.01) v1(41.44,9.19) v1(41.44,4.62) v1(41.44,2.08) v1(42.58,86.28) v1(42.58,83.74) v1(42.71,7.67) v1(42.71,0.81) v1(42.77,32.77) v1(42.77,28.96) v1(42.89,49.78) v1(42.89,34.92) v1(43.02,30.23) v1(42.97,27.76) v1(43.53,32.77) v1(43.66,34.92) v1(43.66,28.96) v1(43.78,30.23) v1(43.78,27.76) v1(43.85,87.55) v1(43.85,85.01) v1(43.91,41.4) v1(43.98,9.19) v1(43.98,4.62) v1(43.98,2.08) v1(44.16,48.51) v1(44.54,47.24) v1(45.12,86.28) v1(45.12,83.74) v1(45.25,7.67) v1(45.25,0.81) v1(46.39,87.55) v1(46.39,85.01) v1(46.52,9.19) v1(46.52,4.62) v1(46.52,2.08) v1(46.7,46.48) v1(47.66,86.28) v1(47.66,83.74) v1(47.79,7.67) v1(47.79,0.81) v1(48.18,45.03) v1(48.3,21.21) v1(48.93,87.55) v1(48.93,85.01) v1(49.06,9.19) v1(49.06,4.62) v1(49.06,2.08) v1(50.2,86.28) v1(50.2,83.74) v1(50.13,64.9) v1(50.26,66.55) v1(50.33,7.67) v1(50.33,0.81) v1(50.39,20.95) v1(50.58,71.66) v1(50.64,70.61) v1(50.64,46.48) v1(50.77,43.05) v1(50.89,40.89) v1(51.02,39.57) v1(51.02,37.85) v1(51.6,4.62) v1(51.6,2.08) v1(51.66,20.57) v1(51.89,40.72) v1(52.04,39.12) v1(52.04,37.59) v1(52.04,9.14) v1(52.16,63.12) v1(52.18,21.26) v1(52.29,35.94) v1(52.29,34.42) v1(52.29,32.89) v1(52.29,31.37) v1(52.93,7.75) v1(52.87,0.81) v1(53.05,29.97) v1(53.43,10.67) v1(53.82,40.64) v1(53.82,39.12) v1(53.82,37.59) v1(53.82,36.07) v1(53.82,34.54) v1(53.82,33.02) v1(53.82,31.5) v1(54.01,87.55) v1(54.01,85.01) v1(54.01,82.47) v1(54.07,80.14) v1(54.14,4.62) v1(54.14,2.08) v1(54.26,78.41) v1(54.45,29.97) v1(54.83,12.45) v1(54.96,10.41) v1(54.96,8.51) v1(55.21,76.2) v1(55.34,40.64) v1(55.34,39.12) v1(55.34,37.59) v1(55.34,36.07) v1(55.34,34.54) v1(55.34,33.02) v1(55.34,31.5) v1(55.41,0.81) v1(55.47,85.98) v1(55.91,87.55) v1(55.85,29.97) v1(56.49,66.29) v1(56.7,20.9) v1(56.68,9.7) v1(56.68,4.62) v1(56.68,2.08) v1(56.74,49.02) v1(56.89,76.2) v1(56.86,40.64) v1(56.86,39.12) v1(56.86,37.59) v1(56.86,36.07) v1(56.86,34.54) v1(56.86,33.02) v1(56.86,31.5) v1(56.86,13.08) v1(56.86,11.81) v1(57.27,43.31) v1(57.5,29.97) v1(57.75,81.53) v1(57.78,14.45) v1(57.95,0.81) v1(58.26,61.59) v1(58.39,76.2) v1(58.39,40.64) v1(58.39,39.12) v1(58.39,37.59) v1(58.39,36.07) v1(58.39,34.54) v1(58.39,33.02) v1(58.39,31.5) v1(58.51,84.45) v1(59.02,80.77) v1(59.02,29.97) v1(59,15.67) v1(59.15,87.38) v1(59.28,85.98) v1(59.28,82.3) v1(59.91,79.12) v1(59.91,40.64) v1(59.91,39.12) v1(59.91,37.59) v1(59.91,36.07) v1(59.91,34.54) v1(59.91,33.02) v1(59.91,31.5) v1(59.94,65.48) v1(60.32,60.88) v1(60.42,49.15) v1(60.49,0.81) v1(60.55,29.97) v1(60.67,20.95) v1(60.93,86.87) v1(61.44,82.55) v1(61.44,39.12) v1(61.44,37.59) v1(61.44,36.07) v1(61.44,34.54) v1(61.44,33.02) v1(61.44,31.5) v1(61.82,80.64) v1(62.12,40.64) v1(62.07,29.97) v1(62.2,83.95) v1(62.32,20.95) v1(62.77,49.29) v1(62.83,39.12) v1(62.83,37.59) v1(62.83,36.07) v1(62.83,34.54) v1(62.83,33.02) v1(62.83,31.5) v1(62.83,16) v1(62.96,46.74) v1(63.03,0.81) v1(63.41,82.34) v1(63.34,56.64) v1(63.59,30.1) v1(63.72,13.97) v1(63.72,12.95) v1(63.72,11.94) v1(63.9,60.88) v1(64.1,65.79) v1(64.09,64.87) v1(64.09,63.6) v1(64.09,62.33) v1(64.55,87.55) v1(64.55,85.01) v1(64.93,79.55) v1(64.99,76.83) v1(65.12,66.8) v1(65.12,65.79) v1(65.11,64.87) v1(65.11,63.6) v1(65.11,62.33) v1(65.25,17.4) v1(65.57,0.81) v1(65.65,60.88) v1(65.82,86.28) v1(66.01,76.83) v1(66.01,66.17) v1(66.01,56.64) v1(66.01,18.16) v1(66.12,64.87) v1(66.12,63.6) v1(66.12,62.33) v1(66.67,72.67) v1(66.9,80.01) v1(66.9,78.11) v1(66.9,66.17) v1(66.9,56.64) v1(67.09,87.55) v1(67.15,60.86) v1(67.79,66.17) v1(68.11,0.81) v1(68.36,86.28) v1(68.36,84.63) v1(68.36,82.09) v1(68.36,79.55) v1(68.49,72.1) v1(68.49,71.21) v1(68.67,66.17) v1(68.74,77.31) v1(68.74,76.29) v1(68.93,46.48) v1(69.18,60.86) v1(69.18,48.9) v1(69.31,39.01) v1(69.63,87.55) v1(69.76,72.1) v1(69.76,71.21) v1(70.01,77.31) v1(70.01,76.29) v1(70.33,81.53) v1(70.65,0.81) v1(70.9,86.28) v1(70.9,79.55) v1(71.03,72.1) v1(71.03,71.21) v1(70.96,56.26) v1(71.28,77.31) v1(71.28,76.29) v1(71.39,6.6) v1(71.72,33.66) v1(71.72,32.13) v1(71.85,56.26) v1(72.17,87.55) v1(72.74,56.26) v1(72.74,33.66) v1(72.74,32.13) v1(72.99,60.83) v1(73.07,77.42) v1(73.12,28.7) v1(73.19,0.81) v1(73.25,19.05) v1(73.25,18.03) v1(73.25,16.76) v1(73.44,86.28) v1(73.44,79.55) v1(73.88,24.51) v1(74.01,60.83) v1(74.01,25.91) v1(74.14,32.13) v1(74.39,27.81) v1(74.52,54.1) v1(74.52,3.05) v1(74.52,1.78) v1(74.71,87.55) v1(74.71,85.01) v1(74.64,37.59) v1(75.02,83.44) v1(75.02,29.21) v1(75.41,54.1) v1(75.66,16.76) v1(75.73,0.81) v1(75.91,26.8) v1(75.98,86.28) v1(76.04,28.32) v1(76.19,6.58) v1(76.29,12.83) v1(76.24,9.91) v1(76.29,8.76) v1(76.42,54.1) v1(76.42,47.62) v1(76.55,60.07) v1(76.8,43.05) v1(76.8,42.29) v1(76.8,23.75) v1(76.93,39.5) v1(76.93,38.73) v1(76.93,37.97) v1(76.93,37.21) v1(77.11,6.38) v1(77.25,87.55) v1(77.31,50.8) v1(77.31,49.66) v1(77.44,16.76) v1(77.64,7.19) v1(78.27,0.81) v1(78.52,86.28) v1(78.45,71.63) v1(78.45,70.61) v1(78.71,21.21) v1(78.71,19.68) v1(78.96,53.98) v1(78.96,53.09) v1(79.47,15.11) v1(79.79,87.55) v1(80.1,51.05) v1(80.1,50.16) v1(80.49,59.18) v1(80.49,58.17) v1(80.87,73.03) v1(81.43,0.89) v1(81.7,7.03) v1(82.01,50.67) v1(82.01,49.78) v1(82.06,4.95) v1(82.14,73.03) v1(82.33,87.55) v1(82.9,68.96) v1(83.03,73.03) v1(83.23,76.78) v1(83.25,78.79) v1(83.35,3.35) v1(83.35,0.81) v1(83.6,86.28) v1(83.6,83.74) v1(83.6,81.2) v1(83.79,71.25) v1(84.17,53.47) v1(84.62,2.08) v1(84.75,79.71) v1(84.8,71.25) v1(84.87,87.55) v1(84.87,85.01) v1(84.88,82.47) v1(85.16,77.37) v1(85.72,27.94) v1(85.82,71.25) v1(85.89,0.81) v1(86.14,86.53) v1(86.84,72.01) v1(86.96,65.53) v1(87.29,70.51) v1(87.41,85.26) v1(87.41,83.36) v1(87.66,76.5) v1(87.66,9.32) v1(87.79,0.81) v1(88.56,48.72) v1(88.61,7.75) v1(88.68,84.25) v1(88.72,58.52) v1(88.77,54.1) v1(88.74,25.4) v1(88.74,24.38) v1(88.74,18.29) v1(88.74,10.59) v1(88.84,56.18) v1(88.87,20.83) v1(89.12,75.49) v1(89.95,82.98) v1(90.08,48.69) v1(90.2,76.5) v1(90.2,73.96) v1(90.2,60.12) v1(90.2,57.58) v1(90.2,55.04) v1(90.2,52.5) v1(90.2,49.96) v1(90.2,22.02) v1(90.2,19.48) v1(90.14,11.56) v1(90.2,9.32) v1(90.2,6.78) v1(90.24,43.28) v1(90.29,40.87) v1(90.37,39.14) v1(90.57,33.55) v1(90.54,32.26) v1(90.57,30.63) v1(90.57,29.24) v1(91.35,47.42) v1(91.35,44.88) v1(91.35,42.34) v1(91.35,39.8) v1(91.35,37.26) v1(91.35,34.72) v1(91.47,81.83) v1(91.47,80.31) v1(91.47,77.77) v1(91.47,75.23) v1(91.47,72.69) v1(91.47,70.15) v1(91.48,68.88) v1(91.47,66.47) v1(91.47,63.93) v1(91.47,61.39) v1(91.47,58.85) v1(91.47,56.31) v1(91.47,53.77) v1(91.47,51.23) v1(91.47,48.69) v1(91.47,46.15) v1(91.47,43.61) v1(91.47,41.07) v1(91.47,38.53) v1(91.47,35.99) v1(91.47,28.37) v1(91.47,25.83) v1(91.47,20.75) v1(91.47,18.21) v1(91.47,10.59) v1(91.47,8.05) v1(91.47,5.51) v1(91.53,29.72) v1(91.64,32.46) v1(91.87,30.89) v1(92.02,22.81) v1(92.17,33.5) v1(92.74,80.56) v1(92.74,79.04) v1(92.74,68.88) v1(92.74,67.74) v1(92.74,65.2) v1(92.74,62.66) v1(92.74,60.12) v1(92.74,57.58) v1(92.74,55.04) v1(92.74,52.5) v1(92.74,49.96) v1(92.74,47.42) v1(92.74,34.72) v1(92.74,32.18) v1(92.74,29.64) v1(92.74,27.1) v1(92.74,24.56) v1(92.74,22.02) v1(92.74,19.48) v1(92.74,6.78) v2(25.24,43.69) v2(26.76,45.21) v2(27.86,46.46) v2(29.05,46.86) v2(30.32,46.86) v2(36.54,34.04) v2(38.19,46.1) v2(38.29,41.59) v2(38.45,33.53) v2(38.55,32.34) v2(39.18,41.59) v2(39.26,24.64) v2(39.59,42.75) v2(39.72,25.22) v2(43.15,36.32) v2(43.15,26.54) v2(43.15,25.4) v2(43.53,45.09) v2(43.91,37.8) v2(43.91,36.32) v2(43.91,25.4) v2(80.74,41.15) v2(84.14,35.97) v2(88.61,36.32) v2(88.72,38.61) v2(88.74,41.91) v2(88.87,40.89) v2(88.87,40.01) v2(89.35,35.69) v2(89.35,34.67) v2(89.76,36.96)
VDD_AUDIO: length 16.4
  TOP w0.381: R66.2 v1(51.32,70.99) ; U5.9 61.04,68.24 v1(61.21,68.07) 61.84,67.44 C158.1 R91.1
  BOTTOM w0.508: v1(51.32,70.99) 52.46,69.85 58.9,69.85 59.59,69.15 C320.1 59.85,69.22 R179.2 v1(61.21,68.07)
ADAC_VOUTL: length 16.7
  TOP w0.203: C350.2 56.74,59.14 R50.1 56.78,58.51 65.81,49.48 66.15,49.48 66.44,49.19 66.44,48.77 66.35,48.69 U1.114
ADAC_VOUTR: length 16.6
  TOP w0.203: U1.116 65.55,48.71 65.37,48.9 65.37,49.15 55.75,58.78 R183.1 55.75,59.72 55.4,60.06 C351.1
AUDIO_L: length 10.7
  TOP w0.203: J34.3 55.97,81.71 55.97,77.98 57.54,76.41 C339.1 R72.2
AUDIO_R: length 14.1
  TOP w0.203: R74.1 C140.1 56.45,75.73 54.96,77.22 54.96,83.7 J34.2
CORE_CTRL: length 3.8
  TOP w0.127: U1.106 71.36,44.98 71.72,45.34 71.72,47.55 R23.2
CPU_CTRL: length 5.6
  TOP w0.127: U1.107 69.72,45.38 69.37,45.72 69.37,48.43 R21.2
CVBS: length 34.5
  TOP w0.203: U1.109 68.4,48.91 67.87,49.44 66.86,49.44 66.39,49.91 66.13,49.91 58.9,57.15 58.9,65.91 59.66,66.67 63.4,66.67 64.48,67.76 64.48,69.34 64.89,69.75 R9.1 C79.1 65.87,70.99 L6.1 65.89,70.97 C80.1
CVBS_OUT: length 17.5
  TOP w0.203: J34.4 58.47,80.01 63.34,80.01 64.3,79.05 64.3,74.23 64.1,74.04 D9.3 64.13,73.43 65.83,73.43 C17.1 65.88,73.38 L6.2 66.88,71.77 C80.2
DDR_ADDR0: length 78.2
  TOP w0.127: U6.N3 31.47,26.93 30.88,26.34 30.88,25.84 30.47,25.43 27.82,25.43 27.64,25.25 27.64,24.74 27.06,24.16 v2(27.06,24.13) 26.37,23.44 26.37,19.05 30.03,15.39 35.81,15.39 36.32,15.9 38.52,15.9 39.58,14.83 53.09,14.83 54.95,16.7 55.82,16.7 57.03,16.7 59.32,18.99 60.22,18.99 60.93,19.69 60.93,20.04 61.5,20.61 61.5,21.68 61.55,21.74 U1.37 ; v2(27.01,40.82) 27.47,41.28 27.47,41.65 27.7,41.87 30.41,41.87 30.83,42.29 30.83,42.66 31.47,43.3 U3.N3
  BOTTOM w0.127: v2(27.01,40.82) 26.76,40.57 26.76,35.71 27.65,34.82 27.65,33.05 26.13,31.52 26.13,27.89 27.64,26.39 27.64,25 27.06,24.42 v2(27.06,24.13)
DDR_ADDR1: length 54
  TOP w0.127: U3.P7 v2(31.07,39.85) ; v1(59.28,20.95) 59.34,21.02 59.34,21.33 59.55,21.54 U1.32 ; U6.P7 v2(31.07,23.44)
  BOTTOM w0.127: v2(31.07,39.85) 31.46,39.46 31.46,38.85 31.28,38.66 31.15,38.66 30.82,38.34 30.82,36.07 31.08,35.81 31.08,31.97 30.7,31.59 30.7,29.84 30.28,29.42 30.28,28.78 31.97,27.08 31.97,25.61 31.07,24.71 v2(31.07,23.44) 31.07,23.2 31.46,22.81 31.46,22.32 31.87,21.92 31.87,21.47 32.09,21.24 32.09,19.56 32.99,18.67 55.59,18.67 57.87,20.95 v1(59.28,20.95)
DDR_ADDR2: length 79.5
  TOP w0.127: U3.P3 30.67,43.35 29.47,42.15 27.5,42.15 v2(27.01,41.66) ; v1(64.48,20.83) 64.48,21.42 64.75,21.69 U1.45 ; U6.P3 30.67,26.89 29.67,25.89 27.51,25.89 27.01,25.4 v2(27.01,25.25)
  BOTTOM w0.127: v2(27.01,41.66) 26.38,41.03 26.38,35.59 27.27,34.7 27.27,33.86 25.37,31.95 25.37,27.56 26.76,26.16 26.76,25.5 v2(27.01,25.25) 26.13,24.37 26.13,21.49 27.91,19.71 27.91,19.02 34.61,12.32 49.87,12.32 53.74,16.19 55.8,16.19 58.09,18.48 61.73,18.48 64.08,20.83 v1(64.48,20.83)
DDR_ADDR3: length 71.1
  TOP w0.127: v2(31.31,42.53) 31.84,43.06 31.84,43.88 U3.N2 ; U1.43 63.95,20.16 61.89,18.1 59.51,18.1 57.35,15.94 56.45,15.94 55.27,15.94 53.4,14.07 38.82,14.07 v1(37.81,15.07) ; v2(31.31,26.12) 31.84,26.65 31.84,27.47 U6.N2
  BOTTOM w0.127: v2(31.31,42.53) 31.31,40.66 29.86,39.2 29.86,38.77 30.34,38.28 30.34,35.62 30.32,35.6 30.32,32.38 28.92,30.99 28.92,29.49 29.07,29.34 29.07,28.85 31.31,26.62 v2(31.31,26.12) 30.27,25.08 30.27,21.54 30.61,21.19 30.61,18.68 31.89,17.4 35.49,17.4 v1(37.81,15.07)
DDR_ADDR4: length 59.2
  TOP w0.127: U3.P8 v2(31.07,39.05) ; U6.P8 v2(31.07,22.64) ; U1.36 61.15,21.78 61.12,21.75 61.12,20.77 60.55,20.2 60.55,19.85 60.06,19.37 59.16,19.37 56.88,17.08 55.66,17.08 54.79,17.08 52.93,15.22 40.47,15.22 v1(39.97,15.71)
  BOTTOM w0.127: v1(39.97,15.71) 37.9,17.78 33.37,17.78 31.97,19.18 31.32,19.18 31.07,19.43 31.07,21.41 31.07,21.41 v2(31.07,22.64) 30.68,23.04 30.68,24.8 31.71,25.84 31.71,26.78 29.32,29.17 29.32,30.98 30.7,32.36 30.7,35.71 30.57,35.84 30.57,38.55 30.77,38.76 v2(31.07,39.05)
DDR_ADDR5: length 81.6
  TOP w0.127: v1(25.95,19.77) 25.95,23.63 27.41,25.09 27.41,25.4 27.67,25.66 30.01,25.66 v2(30.42,26.07) 30.42,26.26 31.05,26.89 31.05,27.46 U6.P2 ; U3.P2 31.05,43.87 31.05,43.29 30.32,42.56 v2(30.32,42.42) ; U1.46 65.15,21.55 64.93,21.33 64.93,20.52 64.48,20.07 v1(64.48,19.43)
  BOTTOM w0.127: v1(25.95,19.77) 25.95,19.36 34.13,11.18 50.35,11.18 54.22,15.05 56.28,15.05 58.57,17.34 62.21,17.34 64.3,19.43 v1(64.48,19.43) ; v2(30.32,42.42) 30.32,40.12 29.46,39.26 29.46,35.91 29.94,35.43 29.94,32.41 28.26,30.73 28.26,28.81 30.42,26.65 v2(30.42,26.07)
DDR_ADDR6: length 56.6
  TOP w0.127: v2(28.67,39.05) 29.47,39.05 U3.R8 ; U6.R8 v2(29.47,22.64) 29.47,20.92 30.7,19.68 30.7,18.38 31.38,17.7 31.66,17.42 41.78,17.42 42.47,16.74 52.3,16.74 54.16,18.61 55.03,18.61 56.24,18.61 57.95,20.31 U1.28
  BOTTOM w0.127: v2(29.47,22.64) 29.47,22.85 29.08,23.24 29.08,26.98 27.6,28.45 27.6,31.04 29.18,32.61 29.18,35.23 28.29,36.12 28.29,38.48 28.67,38.86 v2(28.67,39.05)
DDR_ADDR7: length 79.3
  TOP w0.127: U3.R2 30.24,43.88 30.24,43.28 29.42,42.45 27.17,42.45 26.26,41.54 26.26,36.83 25.19,35.76 25.19,32.56 28.03,29.72 28.67,29.72 29.45,28.93 29.45,28.57 29.87,28.16 U6.R2 30.27,27.45 30.27,26.92 29.46,26.12 27.23,26.12 26.51,25.4 26.51,24.77 25.52,23.77 25.52,19.36 29.87,15.01 35.97,15.01 36.48,15.52 38.36,15.52 39.43,14.45 53.24,14.45 55.11,16.32 55.98,16.32 57.19,16.32 59.35,18.48 61.73,18.48 63.55,20.3 U1.42
DDR_ADDR8: length 58.4
  TOP w0.127: v2(27.84,39.1) 28.19,39.45 U3.T8 ; U6.T8 v2(28.67,22.64) 28.67,22.64 28.67,21.72 28.68,21.71 28.68,19.87 31.12,17.43 31.5,17.04 41.63,17.04 42.31,16.36 52.45,16.36 54.32,18.22 55.19,18.22 56.4,18.22 58.33,20.16 58.33,21.09 58.35,21.11 U1.29
  BOTTOM w0.127: v2(27.84,39.1) 27.53,38.79 27.53,35.92 28.42,35.03 28.42,32.82 26.89,31.29 26.89,28.15 28.46,26.58 28.46,24.75 28.03,24.32 28.03,23.28 v2(28.67,22.64)
DDR_ADDR9: length 83.1
  TOP w0.127: U1.51 67.15,21.58 66.71,21.14 66.71,20.37 64.95,18.61 63.48,18.61 62.21,17.34 59.83,17.34 57.67,15.18 55.58,15.18 53.61,13.21 v1(50.13,13.21) ; v1(33.24,14.55) 29.8,14.55 25.14,19.21 25.14,23.97 26.13,24.96 26.13,25.53 26.95,26.35 29.22,26.35 29.87,26.99 U6.R3 29.87,27.28 29.53,27.62 29.53,27.92 29.2,28.25 28.74,28.25 24.81,32.18 24.81,36.02 25.88,37.08 25.88,41.73 26.93,42.79 29.32,42.79 29.87,43.33 U3.R3
  BOTTOM w0.127: v1(50.13,13.21) 49.62,12.7 35.09,12.7 v1(33.24,14.55)
DDR_ADDR10: length 46.6
  TOP w0.127: U6.L7 v2(32.67,24.24) ; U3.L7 v2(32.67,40.65) ; v1(53.69,19.88) 53.79,19.88 53.82,19.9 54.37,19.9 55.5,21.03 55.5,21.4 55.55,21.46 U1.22
  BOTTOM w0.127: v2(32.67,40.65) 33.06,40.26 33.06,39.69 32.98,39.61 32.98,28.89 33.11,28.76 33.11,24.69 v2(32.67,24.24) 33.07,23.84 33.07,22.43 33.21,22.28 33.21,20.35 33.75,19.81 53.59,19.81 53.65,19.88 v1(53.69,19.88)
DDR_ADDR11: length 57
  TOP w0.127: U3.R7 v2(29.47,39.85) ; U1.23 55.95,21.32 55.88,21.25 55.88,20.87 54.37,19.37 53.73,19.37 v1(52.52,18.16) ; U6.R7 v2(29.47,23.44)
  BOTTOM w0.127: v2(29.47,39.85) 29.17,39.56 29.17,38.86 28.67,38.35 28.67,36.22 29.56,35.33 29.56,32.51 27.93,30.89 27.93,28.63 29.47,27.09 v2(29.47,23.44) 29.47,23.33 29.86,22.94 29.86,22.4 29.46,22 29.46,21.53 29.05,21.12 29.05,19.56 31.59,17.02 34.89,17.02 37.31,14.61 48.54,14.61 52.09,18.16 v1(52.52,18.16)
DDR_ADDR12: length 50.6
  TOP w0.127: U6.N7 v2(31.87,23.44) ; U3.N7 v2(31.87,39.85) ; v1(55.34,19.11) 56.21,19.11 57.55,20.45 U1.27
  BOTTOM w0.127: v2(31.87,39.85) 31.87,39.63 32.3,39.2 32.3,38.69 31.87,38.26 31.87,37.88 32.3,37.45 32.3,29.85 31.87,29.42 31.87,28.51 32.5,27.87 32.5,25.18 31.87,24.55 v2(31.87,23.44) 31.87,23.22 32.26,22.82 32.26,22.27 32.68,21.85 32.68,19.61 33.24,19.05 55.28,19.05 v1(55.34,19.11)
DDR_ADDR13: length 84.9
  TOP w0.127: U3.T3 26.48,43.45 25.11,42.08 25.11,37.59 24.05,36.53 24.05,31.67 28.29,27.43 28.8,27.43 29.07,27.16 U6.T3 28.99,26.96 28.16,26.96 27.18,27.94 25.62,27.94 25.23,27.55 25.23,25.13 24.38,24.28 24.38,18.89 29.57,13.69 53.56,13.69 55.43,15.56 57.51,15.56 59.67,17.72 62.05,17.72 63.32,18.99 64.8,18.99 66.33,20.53 66.33,21.3 66.75,21.72 U1.50
DDR_ADDR14: length 59.9
  TOP w0.127: U3.T7 v2(28.67,39.85) ; U6.T7 28.76,23.84 v2(28.54,23.62) 28.42,23.62 28.16,23.37 28.16,19.85 30.73,17.27 31.35,16.66 41.47,16.66 42.15,15.98 52.61,15.98 54.48,17.84 55.34,17.84 56.56,17.84 58.73,20.02 58.73,20.57 58.73,21.26 59.15,21.68 U1.31
  BOTTOM w0.127: v2(28.67,39.85) 28.23,39.42 28.23,38.94 27.91,38.61 27.91,36.02 28.8,35.13 28.8,32.72 27.27,31.19 27.27,28.27 28.74,26.8 28.74,24.05 28.54,23.84 v2(28.54,23.62)
DDR_ADDR15: length 49.5
  TOP w0.127: U1.26 57.15,20.68 56.28,19.81 v1(56.1,19.81) ; U6.M7 v2(32.67,23.44) ; U3.M7 v2(31.87,40.65)
  BOTTOM w0.127: v1(56.1,19.81) 54.47,19.81 54.09,19.43 33.5,19.43 32.93,19.99 32.93,22.08 32.67,22.34 v2(32.67,23.44) 32.23,23.89 32.23,24.38 32.81,24.96 32.81,28.48 32.66,28.62 32.66,39.27 32.27,39.66 32.27,40.06 31.87,40.47 v2(31.87,40.65)
DDR_BA0: length 85.9
  TOP w0.127: U3.M2 32.68,43.84 32.68,42.89 31.03,41.24 28.44,41.24 26.64,39.43 26.64,36.58 25.57,35.51 25.57,32.82 28.16,30.23 28.8,30.23 29.3,29.72 30.81,29.72 31.08,29.45 31.08,29.03 31.08,29.03 31.08,28.51 31.36,28.23 31.66,28.23 31.89,28 32.12,28 U6.M2 32.27,27.7 32.61,27.35 32.61,26.29 31.11,24.79 28.35,24.79 26.79,23.23 v1(26.79,19.34) ; v1(65.31,20.13) 65.31,21.17 65.55,21.41 U1.47
  BOTTOM w0.127: v1(26.79,19.34) 26.79,19.06 34.29,11.56 50.19,11.56 54.06,15.43 56.12,15.43 58.41,17.72 62.05,17.72 64.27,19.94 65.12,19.94 v1(65.31,20.13)
DDR_BA1: length 52.6
  TOP w0.127: U6.N8 v2(31.87,22.64) 31.87,20.85 31.21,20.19 31.21,18.41 31.82,17.81 41.94,17.81 42.63,17.12 52.14,17.12 54,18.99 54.53,18.99 56.26,20.71 56.26,21.09 56.35,21.18 U1.24 ; U3.N8 v2(31.87,39.05)
  BOTTOM w0.127: v2(31.87,22.64) 31.87,22.82 31.48,23.21 31.48,24.63 32.22,25.38 32.22,27.54 31.08,28.69 31.08,31.41 31.46,31.79 31.46,35.89 31.08,36.28 31.08,38.19 31.31,38.42 31.5,38.42 31.87,38.79 v2(31.87,39.05)
DDR_BA2: length 73.5
  TOP w0.127: v1(59.72,20.19) 59.72,21.17 59.95,21.4 U1.33 ; U6.M3 32.27,26.46 30.91,25.1 28.11,25.1 v2(28.03,25.03) ; v2(28.03,41.43) 28.14,41.54 30.91,41.54 32.27,42.9 U3.M3
  BOTTOM w0.127: v1(59.72,20.19) 59.53,20 57.46,20 55.17,17.71 52.18,17.71 48.69,14.22 37.09,14.22 34.68,16.64 31.43,16.64 28.67,19.4 28.67,20.32 27.65,21.34 27.65,24.65 v2(28.03,25.03) 28.03,26.5 26.51,28.02 26.51,31.39 28.03,32.92 28.03,34.92 27.15,35.81 27.15,39.75 28.03,40.64 v2(28.03,41.43)
DDR_CASN: length 84.4
  TOP w0.127: v1(60.93,19.05) 61.3,19.05 62.01,19.75 62.01,20.01 62.77,20.77 62.77,21.14 62.75,21.16 U1.40 ; U6.K3 33.87,27.36 33.42,27.81 33.42,28.99 v2(33.77,29.34) 33.77,29.59 30.17,33.18 v2(27.19,33.18) ; U3.K3 v2(34.27,43.05)
  BOTTOM w0.127: v2(33.77,29.34) 34.46,30.03 34.46,31.12 34.28,31.3 34.28,37.5 34.48,37.7 34.48,41.08 34.24,41.32 34.24,41.32 34.01,41.55 34.01,41.55 33.97,41.59 33.97,42.76 v2(34.27,43.05) ; v1(60.93,19.05) 60.74,18.86 57.93,18.86 55.65,16.57 52.66,16.57 49.17,13.08 35.4,13.08 32.35,16.13 31.34,16.13 28.29,19.18 28.29,19.94 26.6,21.63 26.6,24.28 27.41,25.09 27.41,25.42 27.15,25.68 27.15,26.29 25.75,27.69 25.75,31.74 v2(27.19,33.18)
DDR_CKE: length 46.5
  TOP w0.127: U3.K9 v2(33.47,38.25) ; U6.K9 33.87,21.6 v2(34.36,21.12) 34.36,20.98 37.05,18.29 42,18.29 42.78,17.5 51.23,17.5 52.8,19.08 52.8,19.68 53.6,20.49 v1(54.32,20.49) 55.12,21.28 55.12,21.56 55.15,21.6 U1.21
  BOTTOM w0.127: v2(34.36,21.12) 34.36,22.16 33.86,22.65 33.86,23.64 33.96,23.74 33.96,25.6 33.57,25.99 33.57,28.86 33.26,29.17 33.26,38.05 v2(33.47,38.25) ; R38.2 55.4,20.49 v1(54.32,20.49)
DDR_CLK0N: length 44.3
  TOP w0.114: v2(34.45,41.71) 34.67,41.49 34.67,41.37 34.14,40.83 34.14,40.52 U3.K7 ; R35.1 50.48,18.13 50.38,18.03 42.78,18.03 42.15,18.66 37.47,18.66 34.53,21.61 34.53,21.86 34.3,22.08 34.3,23.08 33.87,23.52 U6.K7 33.87,24.35 34.39,24.88 v2(34.69,24.88)
  BOTTOM w0.114: R16.2 34.8,42.16 34.8,41.97 34.55,41.71 v2(34.45,41.71) 34.82,41.35 34.82,25 v2(34.69,24.88) 34.9,24.67 34.9,24.05 34.6,23.75 34.6,23.38 R17.2
DDR_CLK0P: length 44.1
  TOP w0.114: U3.J7 34.4,40.52 34.4,40.72 34.94,41.26 34.94,41.49 v2(35.16,41.71) ; v2(35.4,24.88) 35.26,24.88 34.89,24.51 34.89,24.07 U6.J7 35.04,23.47 35.04,22.01 34.86,21.83 34.86,21.65 37.58,18.93 38.67,18.93 38.84,19.1 38.84,19.22 39.01,19.39 39.24,19.39 39.41,19.22 39.41,19.1 39.58,18.93 39.81,18.93 39.98,19.1 39.98,19.22 40.15,19.39 40.39,19.39 40.55,19.22 40.55,19.1 40.72,18.93 42.26,18.93 42.89,18.3 50.27,18.3 50.35,18.38 R18.1
  BOTTOM w0.114: R16.1 35.32,42.45 35.07,42.2 35.07,41.81 v2(35.16,41.71) 35.08,41.64 35.08,25.19 v2(35.4,24.88) 35.16,24.64 35.16,23.94 34.87,23.64 34.87,23.39 R17.1
DDR_CSN: length 76.2
  TOP w0.127: U3.L2 33.47,43.85 33.47,42.83 31.28,40.65 28.78,40.65 27.4,39.26 27.4,36.07 26.33,35 26.33,33.32 28.42,31.24 29.05,31.24 29.81,30.48 31.7,30.48 32.67,29.51 32.67,28.25 32.81,28.11 32.81,28.1 U6.L2 33.21,27.7 33.21,27.69 33.53,27.38 33.53,26.19 31.57,24.24 28.59,24.24 27.73,23.37 27.73,19.74 30.83,16.63 31.19,16.28 41.31,16.28 41.99,15.6 52.77,15.6 54.64,17.46 55.5,17.46 56.72,17.46 59,19.75 59.91,19.75 60.17,20.01 60.17,21.08 60.35,21.26 U1.34
DDR_DM0: length 8.8
  TOP w0.127: v2(43.16,39.03) 43.87,39.03 44.32,38.58 U1.181 ; v2(38.27,39.85) U3.E7
  BOTTOM w0.127: v2(38.27,39.85) 39.2,40.78 41.74,40.78 43.15,39.37 43.15,39.05 v2(43.16,39.03)
DDR_DM1: length 10.1
  TOP w0.127: U3.D3 v2(39.07,43.85) ; U1.182 44.17,38.18 44.12,38.23 v2(43.32,38.23)
  BOTTOM w0.127: v2(43.32,38.23) 43.66,38.56 43.66,39.5 39.91,43.24 39.68,43.24 v2(39.07,43.85)
DDR_DM2: length 8
  TOP w0.127: U6.E7 37.87,23.89 v2(38.47,24.5) ; U1.215 42.89,24.98 v2(42.31,24.4)
  BOTTOM w0.127: v2(38.47,24.5) 38.84,24.13 42.04,24.13 v2(42.31,24.4)
DDR_DM3: length 7.5
  TOP w0.127: v2(43.4,24.4) 43.53,24.53 U1.216 ; U6.D3 v2(39.3,26.42)
  BOTTOM w0.127: v2(43.4,24.4) 42.94,24.87 42.57,24.87 41.43,26.01 39.7,26.01 v2(39.3,26.42)
DDR_DQ0: length 12.4
  TOP w0.127: U1.167 43.04,44.18 42.39,44.83 42.39,46.1 41.88,46.61 37.94,46.61 37.47,46.14 37.47,43.85 U3.E3
DDR_DQ1: length 11.3
  TOP w0.127: U3.F7 37.46,39.86 37.46,38.45 38.32,37.59 39.34,37.59 42.51,34.42 44,34.42 44.16,34.58 U1.191
DDR_DQ2: length 11.4
  TOP w0.127: U1.164 44,45.38 42.39,46.99 37.56,46.99 36.67,46.1 36.67,44.65 U3.F2
DDR_DQ3: length 11.7
  TOP w0.127: U3.F8 36.68,39.06 36.68,37.95 37.41,37.21 39.08,37.21 42.26,34.04 44.16,34.04 44.31,34.18 U1.192
DDR_DQ4: length 13.2
  TOP w0.127: U3.H3 35.87,43.85 v2(36.67,43.85) ; U1.166 43.27,44.58 42.89,44.96 v2(42.89,45.34)
  BOTTOM w0.127: v2(36.67,43.85) 37.23,44.41 37.23,44.75 37.78,45.3 37.78,46.32 38.19,46.74 42.13,46.74 42.89,45.97 v2(42.89,45.34)
DDR_DQ5: length 13.7
  TOP w0.127: U1.195 44.16,32.98 43.87,33.27 41.75,33.27 38.58,36.45 36.57,36.45 35.08,37.95 35.08,39.06 U3.H8
DDR_DQ6: length 12.3
  TOP w0.127: U1.163 44.18,45.83 42.64,47.37 37.18,47.37 35.85,46.04 35.85,44.67 U3.G2
DDR_DQ7: length 13.5
  TOP w0.127: U3.H7 35.88,39.85 35.88,37.95 37.01,36.81 38.85,36.81 42,33.66 44.04,33.66 44.31,33.38 U1.194
DDR_DQ8: length 8.8
  TOP w0.127: U1.184 44.29,37.38 44.25,37.34 43.15,37.34 v2(42.64,37.85) ; v2(39.07,39.85) U3.D7
  BOTTOM w0.127: v2(42.64,37.85) 42.64,39.24 41.56,40.32 39.53,40.32 39.07,39.86 v2(39.07,39.85)
DDR_DQ9: length 5.8
  TOP w0.127: U1.170 40.17,42.98 39.7,43.45 U3.C3
DDR_DQ10: length 8
  TOP w0.127: U1.185 v2(42.51,36.98) ; v2(39.87,39.85) U3.C8
  BOTTOM w0.127: v2(39.87,39.85) 41.4,39.85 42.13,39.12 42.13,37.23 42.39,36.98 v2(42.51,36.98)
